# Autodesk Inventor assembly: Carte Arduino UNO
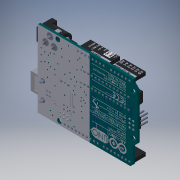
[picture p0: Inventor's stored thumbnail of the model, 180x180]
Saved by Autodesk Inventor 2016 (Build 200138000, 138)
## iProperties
Created: 2016-07
Part Number: Carte Arduino UNO
Material: Générique
Description: SolidWorks IGES file using analytic representation for surfaces
Document SubType Name: Assembly
Designer: Bruno
Title: C:\Users\Alexandre\Dropbox\Freelance\2016-01 Mechatronics Art\Projects\Arduino Uno Case\Export\Carte Arduino UNO.IGS
Author: Alexandre
Sending System: SolidWorks 2016
Preprocessor: SolidWorks 2016
Minimum Resolution: 0.0
Sending System Product ID: Carte Arduino UNO.SLDASM
Receiving System Product ID: Carte Arduino UNO.SLDASM
Sent Units: Millimeter
Translation Standard: IGES 5.3
Model Creation Time: 2016-07-03
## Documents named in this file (34)
- D:\Cours\1-Cours-2017-18\2SI\projet\Inventor\Arduino\Carte Arduino UNO.iam
- D:\Cours\1-Cours-2017-18\2SI\projet\Inventor\arduino-uno-8.snapshot.5\Carte.ipt
- D:\Cours\1-Cours-2017-18\2SI\projet\Inventor\arduino-uno-8.snapshot.5\Reset.ipt
- D:\Cours\1-Cours-2017-18\2SI\projet\Inventor\arduino-uno-8.snapshot.5\Alimentation.ipt
- D:\Cours\1-Cours-2017-18\2SI\projet\Inventor\arduino-uno-8.snapshot.5\Perle de filtre BLM21.ipt
- D:\Cours\1-Cours-2017-18\2SI\projet\Inventor\arduino-uno-8.snapshot.5\Prise_usb.ipt
- D:\Cours\1-Cours-2017-18\2SI\projet\Inventor\arduino-uno-8.snapshot.5\Fusible rearmable mf-msmf050-2.ipt
- D:\Cours\1-Cours-2017-18\2SI\projet\Inventor\arduino-uno-8.snapshot.5\Diode CD1206.ipt
- D:\Cours\1-Cours-2017-18\2SI\projet\Inventor\arduino-uno-8.snapshot.5\Condensateur 603-2.ipt
- D:\Cours\1-Cours-2017-18\2SI\projet\Inventor\arduino-uno-8.snapshot.5\Condensateur MLC.ipt
- D:\Cours\1-Cours-2017-18\2SI\projet\Inventor\arduino-uno-8.snapshot.5\Resistance 220.ipt
- D:\Cours\1-Cours-2017-18\2SI\projet\Inventor\arduino-uno-8.snapshot.5\Semiconducteur Fairchild.ipt
- D:\Cours\1-Cours-2017-18\2SI\projet\Inventor\arduino-uno-8.snapshot.5\Condensateur 603.ipt
- D:\Cours\1-Cours-2017-18\2SI\projet\Inventor\arduino-uno-8.snapshot.5\Resistance 105.ipt
- D:\Cours\1-Cours-2017-18\2SI\projet\Inventor\arduino-uno-8.snapshot.5\Circuit integre ATMEGA 16U2.ipt
- D:\Cours\1-Cours-2017-18\2SI\projet\Inventor\arduino-uno-8.snapshot.5\Socket microcontroller.ipt
- D:\Cours\1-Cours-2017-18\2SI\projet\Inventor\arduino-uno-8.snapshot.5\Microcontroller.ipt
- D:\Cours\1-Cours-2017-18\2SI\projet\Inventor\arduino-uno-8.snapshot.5\Header 2 pins.ipt
- D:\Cours\1-Cours-2017-18\2SI\projet\Inventor\arduino-uno-8.snapshot.5\Circuit integre LD50.ipt
- D:\Cours\1-Cours-2017-18\2SI\projet\Inventor\arduino-uno-8.snapshot.5\Squartz cristal.ipt
- D:\Cours\1-Cours-2017-18\2SI\projet\Inventor\arduino-uno-8.snapshot.5\Circuit integre IP2985.ipt
- D:\Cours\1-Cours-2017-18\2SI\projet\Inventor\arduino-uno-8.snapshot.5\Bornes octogonales.ipt
- D:\Cours\1-Cours-2017-18\2SI\projet\Inventor\arduino-uno-8.snapshot.5\Amplificateur operationnel LMV358.ipt
- D:\Cours\1-Cours-2017-18\2SI\projet\Inventor\arduino-uno-8.snapshot.5\Condensateur 47uf.ipt
- D:\Cours\1-Cours-2017-18\2SI\projet\Inventor\arduino-uno-8.snapshot.5\Diode de redressement m7.ipt
- D:\Cours\1-Cours-2017-18\2SI\projet\Inventor\arduino-uno-8.snapshot.5\Power pins.ipt
- D:\Cours\1-Cours-2017-18\2SI\projet\Inventor\arduino-uno-8.snapshot.5\Analog pins 0-5.ipt
- D:\Cours\1-Cours-2017-18\2SI\projet\Inventor\arduino-uno-8.snapshot.5\Resistance 103.ipt
- D:\Cours\1-Cours-2017-18\2SI\projet\Inventor\arduino-uno-8.snapshot.5\Bornes rectangulaires.ipt
- D:\Cours\1-Cours-2017-18\2SI\projet\Inventor\arduino-uno-8.snapshot.5\Diode SMD.ipt
- D:\Cours\1-Cours-2017-18\2SI\projet\Inventor\arduino-uno-8.snapshot.5\Resistance 102.ipt
- D:\Cours\1-Cours-2017-18\2SI\projet\Inventor\arduino-uno-8.snapshot.5\Quartz 16MHz.ipt
- D:\Cours\1-Cours-2017-18\2SI\projet\Inventor\arduino-uno-8.snapshot.5\Digital pins 0-7.ipt
- D:\Cours\1-Cours-2017-18\2SI\projet\Inventor\arduino-uno-8.snapshot.5\Digital pins 8-13.ipt
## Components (52 placed, 33 different names)
1. Carte
2. Reset
3. Alimentation
4. Perle de filtre BLM21
5. Prise_usb
6. Fusible rearmable mf-msmf050-2
7. Diode CD1206
8. Diode CD1206:1
9. Condensateur 603-2
10. Condensateur MLC
11. Resistance 220
12. Semiconducteur Fairchild
13. Condensateur MLC:1
14. Condensateur 603
15. Condensateur 603:1
16. Resistance 105
17. Condensateur 603:2
18. Condensateur 603:3
19. Condensateur 603:4
20. Circuit integre ATMEGA 16U2
21. Socket microcontroller
22. Microcontroller
23. Header 2 pins
24. Header 2 pins:1
25. Circuit integre LD50
26. Squartz cristal
27. Circuit integre IP2985
28. Bornes octogonales
29. Condensateur 603:5
30. Condensateur 603:6
31. Amplificateur operationnel LMV358
32. Condensateur 47uf
33. Condensateur 47uf:1
34. Diode de redressement m7
35. Perle de filtre BLM21:1
36. Condensateur 603:7
37. Power pins
38. Analog pins 0-5
39. Resistance 103
40. Bornes rectangulaires
41. Diode SMD
42. Diode SMD:1
43. Diode SMD:2
44. Resistance 102
45. Quartz 16MHz
46. Resistance 105:1
47. Diode SMD:3
48. Resistance 102:1
49. Condensateur 603:8
50. Digital pins 0-7
51. Condensateur 603:9
52. Digital pins 8-13
